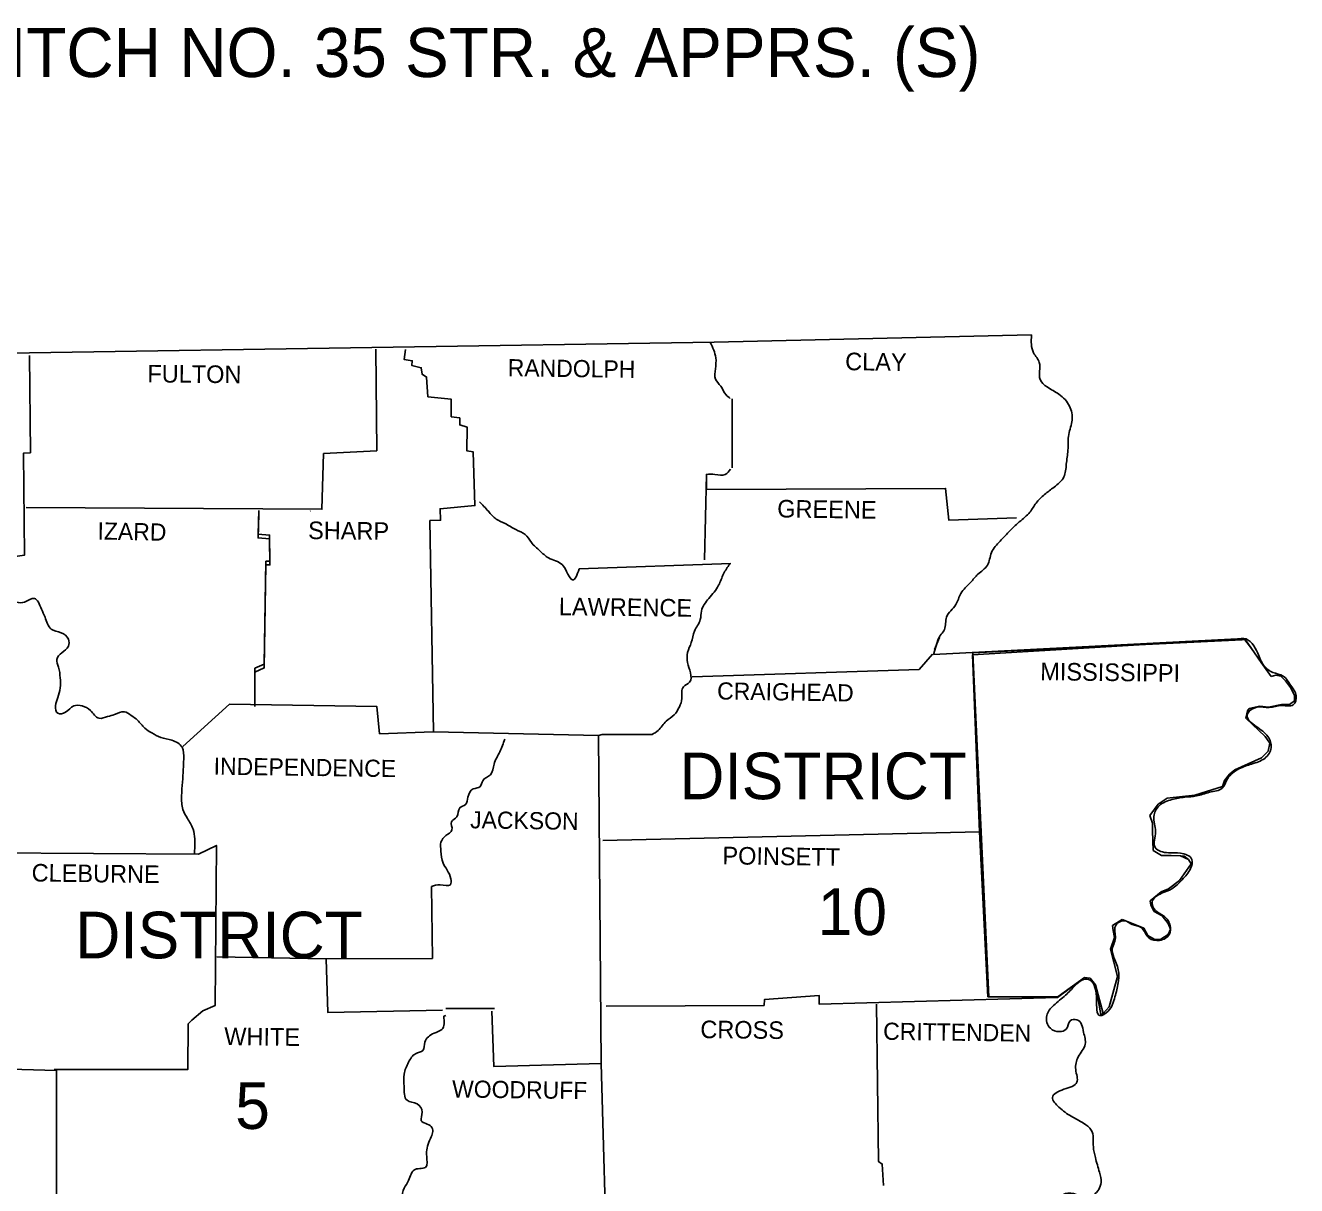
# Model space of a CAD drawing. Extents: x 166 to 3426, y 71 to 2074.
# Drawn here: x 2999.8 to 3303.9, y 1757.5 to 2035 of the extents above; entities that cross this region are included whole.
import ezdxf

# ---------------------------------------------------------------- set-up
doc = ezdxf.new("R2010")
doc.units = 0
for name, color, linetype in [('1', 7, 'Continuous'), ('2', 7, 'Continuous'), ('3', 7, 'Continuous'), ('R_Border', 7, 'Continuous'), ('S_MISC_BOUNDARY', 7, 'Continuous')]:
    doc.layers.add(name, color=color, linetype=linetype)

msp = doc.modelspace()

# ---------------------------------------------------------------- linework, layer by layer
at = {"layer": '1'}
for p, q in [((3217.27, 1885.68), (3218.45, 1888.52)), ((3216.98, 1884.51), (3218.15, 1888.13)), ((3100.35, 1799.78), (3112, 1799.78))]:
    msp.add_line(p, q, dxfattribs=at)
for points in [[(2703.71, 1956.42), (2861.92, 1956.32), (3000.75, 1956.61), (3164.54, 1959.16), (3240.46, 1960.92)], [(3000.75, 1956.03), (3000.95, 1932.74), (2999.28, 1932.64), (2999.58, 1908.28), (2992.73, 1907.3), (2993.32, 1900.75), (2995.66, 1897.71), (2995.47, 1889.98), (2982.16, 1889.5), (2981.67, 1877.56), (2969.54, 1877.17), (2968.95, 1862.69), (2969.64, 1861.51), (2969.93, 1838.42), (2990.87, 1837.05), (2990.58, 1785.49), (3007.21, 1785), (3007.21, 1732.56), (2994.1, 1731.58), (2993.12, 1720.04), (2971.11, 1719.94)], [(3083.62, 1957.49), (3083.82, 1933.23), (3071.1, 1932.55), (3070.71, 1919.24), (2999.97, 1919.63)], [(3090.67, 1957.4), (3090.37, 1955.05), (3092.33, 1954.76), (3092.23, 1953.58), (3094.48, 1953.09), (3094.68, 1951.53), (3095.75, 1950.84), (3096.05, 1946.15), (3101.63, 1945.56), (3101.63, 1941.35), (3103.68, 1941.06), (3103.68, 1939.39), (3105.44, 1938.9), (3105.34, 1933.23), (3106.91, 1932.94), (3107.3, 1920.12), (3098.98, 1919.34), (3099.08, 1916.6), (3096.54, 1916.5), (3097.42, 1866.01), (3136.85, 1865.13), (3137.53, 1786.66), (3111.8, 1785.98), (3111.31, 1799.19)], [(3168.84, 1945.66), (3168.84, 1929.12)], [(3162.19, 1907.11), (3162.68, 1927.56), (3162.68, 1923.94), (3219.91, 1924.23), (3220.7, 1916.6), (3236.84, 1917.18)], [(3055.64, 1918.95), (3055.44, 1913.27), (3058.18, 1913.07), (3058.28, 1906.81), (3057.3, 1906.81), (3056.91, 1882.16), (3054.66, 1881.18), (3054.66, 1872.96)], [(3067.87, 1918.75), (3067.97, 1918.85)], [(3055.64, 1918.06), (3055.44, 1912.39), (3058.18, 1912.19), (3058.28, 1905.93), (3057.3, 1905.93), (3056.91, 1881.28), (3054.66, 1880.3), (3054.66, 1872.08)], [(3132.25, 1904.95), (3168.55, 1906.23)], [(3216.98, 1884.51), (3291.24, 1888.32)], [(3159.25, 1879.12), (3213.55, 1880.89), (3216.78, 1884.6)], [(3226.37, 1884.41), (3228.04, 1842.04), (3229.99, 1802.61)], [(3037.44, 1862.49), (3048.6, 1872.57), (3083.82, 1872.08), (3084.5, 1865.52), (3097.32, 1866.01)], [(3149.67, 1865.33), (3137.73, 1865.33), (3136.85, 1865.13)], [(3228.04, 1842.04), (3137.92, 1839.99)], [(2990.87, 1837.05), (3041.16, 1836.76), (3045.46, 1838.81), (3045.17, 1800.56), (3042.24, 1799.29), (3039.59, 1797.04), (3038.71, 1796.16), (3038.62, 1785.2), (3006.62, 1785.2)], [(3096.93, 1829.03), (3097.12, 1811.81), (3071.69, 1811.71), (3045.56, 1812.2)], [(3071.69, 1811.71), (3072.08, 1798.89), (3099.57, 1799.38)], [(3138.71, 1800.36), (3176.47, 1800.56), (3176.57, 1801.93), (3189.68, 1802.91), (3189.68, 1800.85), (3246.63, 1802.42)], [(3203.38, 1800.85), (3203.87, 1763.18), (3204.75, 1762.6), (3205.04, 1757.51)], [(3100.35, 1798.11), (3099.86, 1798.01)], [(3137.53, 1786.66), (3139, 1733.05), (3115.71, 1732.95), (3115.62, 1730.8), (3108.87, 1730.41), (3108.28, 1719.25), (3100.06, 1719.25)]]:
    msp.add_lwpolyline(points, dxfattribs=at)
for points in [[(3163.59, 1959.15), (3164.93, 1955.44), (3164.83, 1952.8), (3164.83, 1950.35), (3166.1, 1948.69), (3167.37, 1946.63), (3168.35, 1945.75)], [(3240.46, 1960.92), (3240.95, 1956.61), (3242.32, 1954.36), (3242.52, 1950.25), (3244.18, 1948.49), (3247.02, 1946.73), (3249.56, 1943.89), (3250.15, 1940.57), (3249.36, 1937.14), (3249.17, 1933.33), (3248.78, 1930), (3248.19, 1926.97), (3245.84, 1924.52), (3243.59, 1922.76), (3241.54, 1920.71), (3240.07, 1918.55), (3237.53, 1916.21), (3234.98, 1913.76), (3232.93, 1911.61), (3230.87, 1908.87), (3229.89, 1905.83), (3227.64, 1903.68), (3225.88, 1901.73), (3223.53, 1899.08), (3222.36, 1896.44), (3220.11, 1893.41), (3219.62, 1890.47), (3218.15, 1888.13), (3218.06, 1887.73)], [(3168.45, 1928.83), (3167.18, 1927.56), (3164.73, 1927.56), (3162.68, 1927.56)], [(3108.38, 1921), (3110.53, 1918.75), (3112.39, 1916.89), (3114.54, 1915.81), (3117.08, 1914.35), (3119.33, 1913.17), (3120.8, 1911.31), (3122.86, 1909.26), (3124.91, 1907.6), (3128.14, 1906.03), (3129.22, 1904.37), (3130.68, 1902.31), (3132.25, 1904.95)], [(3168.25, 1906.13), (3166.79, 1903.78), (3165.61, 1901.04), (3163.26, 1897.91), (3161.5, 1894.88), (3161.21, 1892.82), (3159.84, 1890.08), (3159.06, 1887.34), (3158.18, 1884.99), (3158.18, 1882.55), (3158.86, 1880.1), (3158.67, 1877.85), (3157.2, 1876.78), (3156.81, 1873.94), (3156.22, 1871.98), (3154.95, 1870.03), (3153.09, 1868.56), (3151.13, 1866.31), (3149.67, 1865.33)], [(2995.66, 1897.71), (2999.58, 1897.03), (3001.93, 1897.91), (3003.59, 1895.37), (3004.47, 1893.41), (3005.94, 1890.57), (3008.29, 1889.69), (3010.05, 1888.13), (3010.05, 1886.46), (3008.48, 1884.9), (3007.31, 1883.33), (3007.7, 1881.47), (3008.09, 1878.93), (3008.09, 1876.48), (3007.5, 1874.23), (3007.01, 1872.18), (3007.5, 1870.42), (3009.36, 1870.71), (3011.32, 1872.18), (3013.37, 1872.18), (3015.33, 1871.1), (3017.38, 1869.24), (3019.44, 1869.63), (3021.1, 1870.12), (3023.45, 1870.81), (3025.11, 1869.93), (3026.58, 1868.75), (3028.34, 1866.89), (3030.01, 1865.72), (3032.16, 1864.64), (3034.8, 1863.96), (3037.25, 1862.3), (3037.64, 1859.46), (3037.54, 1857.01), (3037.34, 1853.98), (3037.15, 1850.65), (3037.44, 1847.42), (3038.52, 1845.27), (3039.89, 1842.73), (3040.28, 1840.38), (3040.18, 1836.66)], [(3290.16, 1888.22), (3291.24, 1888.32), (3294.57, 1884.8), (3296.03, 1881.86), (3298.19, 1880.2), (3300.63, 1879.32), (3302.49, 1877.07), (3303.76, 1874.62), (3303.08, 1872.47), (3300.34, 1872.28), (3297.31, 1871.79), (3294.37, 1871.88), (3292.02, 1869.93), (3294.18, 1867.29), (3297.01, 1864.84), (3297.8, 1862.2), (3296.23, 1859.65), (3293.1, 1858.28), (3290.07, 1857.11), (3287.33, 1854.76), (3286.05, 1852.51), (3283.02, 1851.53), (3279.89, 1850.65), (3277.15, 1850.36), (3274.02, 1849.77), (3270.99, 1848.3), (3269.72, 1845.76), (3270.11, 1842.14), (3270.01, 1838.32), (3273.24, 1837.05), (3276.08, 1836.95), (3278.81, 1835.49), (3278.52, 1833.33), (3276.47, 1830.6), (3274.02, 1828.44), (3271.57, 1827.37), (3269.32, 1825.31), (3270.11, 1823.26), (3272.16, 1821.89), (3273.63, 1819.64), (3273.43, 1817.58), (3271.09, 1816.11), (3268.54, 1816.7), (3266.68, 1819.15), (3264.53, 1819.93), (3262.67, 1820.81), (3260.52, 1819.54), (3260.52, 1816.7), (3259.74, 1813.67), (3260.42, 1811.42), (3261.3, 1808.29), (3261.2, 1805.94), (3260.42, 1802.61), (3258.76, 1799.19), (3256.8, 1798.11), (3256.02, 1801.83), (3255.63, 1804.86), (3254.45, 1806.62), (3252.89, 1806.72), (3250.83, 1805.25), (3248.58, 1803), (3245.74, 1800.56), (3244.08, 1798.11), (3244.96, 1795.08), (3247.11, 1794.3), (3248.78, 1794.88), (3249.66, 1796.84), (3251.32, 1797.13), (3252.89, 1794.1)], [(3114.44, 1864.25), (3113.27, 1861.22), (3111.9, 1858.28), (3111.02, 1855.74), (3109.16, 1854.27), (3108.57, 1852.9), (3106.91, 1852.32), (3105.64, 1850.36), (3105.05, 1848.6), (3103.68, 1847.82), (3103, 1845.66), (3101.72, 1844.49), (3101.82, 1842.53), (3100.35, 1841.16), (3099.18, 1839.6), (3099.18, 1837.44), (3099.67, 1834.61), (3100.65, 1832.94), (3101.53, 1830.79), (3101.43, 1829.42), (3098.98, 1829.42), (3096.93, 1829.03)], [(3099.86, 1798.01), (3099.37, 1794.79), (3097.52, 1793.91), (3095.36, 1791.75), (3094.87, 1789.8), (3093.11, 1789.01), (3091.45, 1786.96), (3090.37, 1784.12), (3090.37, 1781.19), (3091.06, 1777.86), (3093.5, 1776.98), (3094.68, 1775.02), (3094.48, 1772.97), (3096.83, 1771.6), (3097.22, 1770.42), (3096.83, 1769.15), (3095.75, 1765.53), (3095.85, 1763.09), (3095.66, 1762.01), (3093.02, 1761.32), (3091.45, 1758.68), (3090.37, 1756.82), (3089.98, 1754.38), (3090.28, 1752.62), (3089.49, 1751.25), (3089.2, 1749.19), (3088.22, 1747.43), (3087.34, 1745.77), (3088.32, 1743.81), (3088.03, 1742.44), (3087.44, 1740.29), (3087.93, 1739.6)], [(3252.89, 1794.1), (3253.28, 1791.26), (3251.62, 1788.23), (3251.03, 1785.2), (3251.32, 1782.16), (3248.19, 1780.5), (3245.45, 1778.54), (3247.02, 1776.2), (3249.95, 1774.04), (3252.89, 1772.38), (3254.75, 1770.72), (3255.24, 1766.71), (3255.72, 1764.16), (3256.7, 1760.64), (3257.09, 1758.19), (3255.33, 1755.26), (3253.28, 1754.67), (3251.13, 1755.36), (3248.58, 1755.55), (3246.53, 1753.59), (3245.06, 1750.86), (3243.59, 1748.12), (3242.52, 1745.77), (3241.44, 1743.22), (3239.29, 1740.29), (3236.65, 1739.8), (3233.51, 1739.02), (3231.66, 1736.86), (3231.95, 1733.24), (3233.71, 1730.8), (3235.08, 1727.76), (3236.06, 1725.12), (3235.57, 1721.8), (3234.2, 1719.35), (3232.44, 1717.88), (3231.66, 1714.75), (3230.38, 1712.4), (3229.21, 1711.62), (3226.86, 1711.82), (3224.32, 1712.31), (3222.16, 1712.11), (3220.11, 1711.03), (3218.06, 1711.72), (3215.9, 1714.07), (3214.14, 1715.83), (3212.19, 1716.51), (3210.13, 1715.44), (3209.74, 1712.21), (3210.72, 1708.88), (3211.6, 1704.38), (3210.72, 1701.64), (3210.42, 1697.14)]]:
    msp.add_spline(points, degree=3, dxfattribs=at)
at = {"layer": 'S_MISC_BOUNDARY'}
for p, q in [((3290.16, 1888.22), (3226.37, 1884.41)), ((3226.44, 1884.86), (3290.81, 1888.03)), ((3290.31, 1888.24), (3290.16, 1888.22)), ((3291.24, 1888.32), (3290.31, 1888.24)), ((3290.81, 1888.03), (3291.37, 1888.06)), ((3293.06, 1885.95), (3291.24, 1888.32)), ((3291.37, 1888.06), (3291.82, 1887.74)), ((3291.82, 1887.74), (3293.06, 1885.95)), ((3293.06, 1885.95), (3295.41, 1882.57)), ((3295.41, 1882.57), (3293.06, 1885.95)), ((3230.26, 1802.6), (3226.44, 1884.86)), ((3295.41, 1882.57), (3297.76, 1879.19)), ((3297.76, 1879.19), (3295.41, 1882.57)), ((3297.76, 1879.19), (3298.93, 1879.51)), ((3298.93, 1879.51), (3297.76, 1879.19)), ((3298.93, 1879.51), (3300.13, 1879.31)), ((3300.13, 1879.31), (3298.93, 1879.51)), ((3300.13, 1879.31), (3301.22, 1878.2)), ((3301.22, 1878.2), (3300.13, 1879.31)), ((3301.22, 1878.2), (3302.44, 1876.57)), ((3302.44, 1876.57), (3301.22, 1878.2)), ((3302.44, 1876.57), (3303.37, 1874.77)), ((3303.37, 1874.77), (3302.44, 1876.57)), ((3303.38, 1873.39), (3302.17, 1872.53)), ((3302.17, 1872.53), (3303.38, 1873.39)), ((3303.37, 1874.77), (3303.38, 1873.39)), ((3303.38, 1873.39), (3303.37, 1874.77)), ((3292.13, 1871.02), (3291.68, 1869.22)), ((3291.68, 1869.22), (3292.03, 1870.18)), ((3292.03, 1870.18), (3292.09, 1870.35)), ((3292.09, 1870.35), (3292.54, 1871.57)), ((3292.54, 1871.57), (3292.13, 1871.02)), ((3295.05, 1872.12), (3292.54, 1871.57)), ((3292.54, 1871.57), (3295.05, 1872.12)), ((3297.13, 1871.88), (3295.05, 1872.12)), ((3295.05, 1872.12), (3297.13, 1871.88)), ((3300.28, 1872.51), (3297.13, 1871.88)), ((3297.13, 1871.88), (3300.28, 1872.51)), ((3302.17, 1872.53), (3300.28, 1872.51)), ((3300.28, 1872.51), (3302.17, 1872.53)), ((3291.68, 1869.22), (3296.38, 1864.85)), ((3296.38, 1864.85), (3291.68, 1869.22)), ((3296.38, 1864.85), (3297.46, 1863.25)), ((3297.46, 1863.25), (3296.38, 1864.85)), ((3297.04, 1861.36), (3295.44, 1859.75)), ((3295.44, 1859.75), (3297.04, 1861.36)), ((3297.46, 1863.25), (3297.04, 1861.36)), ((3297.04, 1861.36), (3297.46, 1863.25)), ((3295.44, 1859.75), (3289.06, 1856.92)), ((3289.06, 1856.92), (3295.44, 1859.75)), ((3287.8, 1855.85), (3286.65, 1854.36)), ((3286.65, 1854.36), (3287.8, 1855.85)), ((3289.06, 1856.92), (3287.8, 1855.85)), ((3287.8, 1855.85), (3289.06, 1856.92)), ((3286.16, 1852.93), (3279.52, 1850.83)), ((3286.65, 1854.36), (3286.16, 1852.93)), ((3286.16, 1852.93), (3286.65, 1854.36)), ((3272.94, 1850.13), (3270.72, 1848.72)), ((3270.72, 1848.72), (3272.94, 1850.13)), ((3279.52, 1850.83), (3272.94, 1850.13)), ((3272.94, 1850.13), (3279.52, 1850.83)), ((3270.72, 1848.72), (3268.77, 1845.96)), ((3268.77, 1845.96), (3270.72, 1848.72)), ((3268.77, 1845.96), (3269.38, 1844.17)), ((3269.38, 1844.17), (3268.77, 1845.96)), ((3269.38, 1844.17), (3269.38, 1842.29)), ((3269.38, 1842.29), (3269.38, 1844.17)), ((3269.38, 1842.29), (3269.56, 1837.62)), ((3269.56, 1837.62), (3269.38, 1842.29)), ((3269.56, 1837.62), (3271.52, 1836.44)), ((3271.52, 1836.44), (3269.56, 1837.62)), ((3271.52, 1836.44), (3273.82, 1836.37)), ((3273.82, 1836.37), (3271.52, 1836.44)), ((3273.82, 1836.37), (3276.11, 1836.3)), ((3276.11, 1836.3), (3273.82, 1836.37)), ((3278.67, 1834.41), (3275.86, 1830.41)), ((3275.86, 1830.41), (3278.67, 1834.41)), ((3276.11, 1836.3), (3276.94, 1836.27)), ((3278.02, 1835.47), (3276.11, 1836.3)), ((3276.94, 1836.27), (3278.02, 1835.47)), ((3278.02, 1835.47), (3278.67, 1834.41)), ((3278.67, 1834.41), (3278.02, 1835.47)), ((3271.5, 1827.68), (3268.87, 1825.55)), ((3268.87, 1825.55), (3271.5, 1827.68)), ((3273.22, 1828.41), (3271.5, 1827.68)), ((3271.5, 1827.68), (3273.22, 1828.41)), ((3275.86, 1830.41), (3273.22, 1828.41)), ((3273.22, 1828.41), (3275.86, 1830.41)), ((3268.87, 1825.55), (3268.96, 1824.55)), ((3268.96, 1824.55), (3268.87, 1825.55)), ((3268.96, 1824.55), (3269.77, 1823.02)), ((3269.77, 1823.02), (3268.96, 1824.55)), ((3269.77, 1823.02), (3271.69, 1821.96)), ((3271.69, 1821.96), (3269.77, 1823.02)), ((3271.69, 1821.96), (3273.18, 1820.16)), ((3273.18, 1820.16), (3271.69, 1821.96)), ((3262.17, 1821.14), (3259.84, 1819.64)), ((3259.84, 1819.64), (3262.17, 1821.14)), ((3259.84, 1819.64), (3259.96, 1818.51)), ((3259.96, 1818.51), (3259.84, 1819.64)), ((3259.96, 1818.51), (3260.3, 1816.83)), ((3260.3, 1816.83), (3259.96, 1818.51)), ((3264.4, 1820.23), (3262.17, 1821.14)), ((3262.17, 1821.14), (3264.4, 1820.23)), ((3267.29, 1819.04), (3264.4, 1820.23)), ((3264.4, 1820.23), (3267.29, 1819.04)), ((3268.24, 1817.29), (3267.29, 1819.04)), ((3267.29, 1819.04), (3268.24, 1817.29)), ((3273.69, 1818.75), (3273.11, 1817.5)), ((3273.11, 1817.5), (3273.69, 1818.75)), ((3273.18, 1820.16), (3273.69, 1818.75)), ((3273.69, 1818.75), (3273.18, 1820.16)), ((3260.3, 1816.83), (3259.31, 1814)), ((3259.31, 1814), (3260.3, 1816.83)), ((3269.98, 1816.31), (3268.24, 1817.29)), ((3268.24, 1817.29), (3269.98, 1816.31)), ((3271.38, 1816.37), (3269.98, 1816.31)), ((3269.98, 1816.31), (3271.38, 1816.37)), ((3273.11, 1817.5), (3271.38, 1816.37)), ((3271.38, 1816.37), (3273.11, 1817.5)), ((3259.31, 1814), (3261.05, 1807.5)), ((3261.05, 1807.5), (3259.31, 1814)), ((3246.63, 1802.42), (3253.09, 1807.19)), ((3253.09, 1807.19), (3246.81, 1802.72)), ((3254.51, 1807.09), (3253.09, 1807.19)), ((3253.09, 1807.19), (3254.51, 1807.09)), ((3255.79, 1805.51), (3254.51, 1807.09)), ((3254.51, 1807.09), (3255.79, 1805.51)), ((3261.05, 1807.5), (3258.99, 1800.18)), ((3258.99, 1800.18), (3261.05, 1807.5)), ((3257.01, 1798.41), (3255.79, 1805.51)), ((3255.79, 1805.51), (3257.56, 1798.6)), ((3229.99, 1802.61), (3246.63, 1802.42)), ((3246.81, 1802.72), (3230.26, 1802.6)), ((3258.99, 1800.18), (3257.56, 1798.6)), ((3257.56, 1798.6), (3258.99, 1800.18)), ((3257.56, 1798.6), (3257.01, 1798.41))]:
    msp.add_line(p, q, dxfattribs=at)
for points in [[(3226.37, 1884.41), (3228.25, 1842.05), (3229.99, 1802.61)], [(3279.52, 1850.83), (3281.02, 1851.31), (3286.16, 1852.93)]]:
    msp.add_lwpolyline(points, dxfattribs=at)

# ---------------------------------------------------------------- texts
at = {"layer": '2'}
for s, height, rotation, p in [('CLAY', 4.206, 359.2258, (3195.85, 1952.5)), ('FULTON', 4.206, 359.4996, (3028.93, 1949.57)), ('RANDOLPH', 4.109, 359.2583, (3115.13, 1951.04)), ('GREENE', 4.207, 359.2361, (3179.6, 1917.28)), ('IZARD', 4.108, 358.9258, (3016.99, 1912)), ('SHARP', 4.206, 359.3905, (3067.38, 1912.1)), ('LAWRENCE', 4.207, 359.2678, (3127.36, 1893.9)), ('MISSISSIPPI', 4.2062, 359.3097, (3242.52, 1878.34)), ('CRAIGHEAD', 4.109, 359.1159, (3165.22, 1873.74)), ('INDEPENDENCE', 4.1081, 359.2187, (3044.78, 1855.74)), ('JACKSON', 4.108, 359.1352, (3106.13, 1842.92)), ('POINSETT', 4.206, 359.1987, (3166.49, 1834.31)), ('CLEBURNE', 4.206, 359.2535, (3001.24, 1830.2)), ('WHITE', 4.207, 359.3139, (3047.32, 1791.07)), ('CROSS', 4.206, 359.3839, (3161.21, 1792.73)), ('CRITTENDEN', 4.109, 359.213, (3204.94, 1792.34)), ('WOODRUFF', 4.108, 359.2748, (3101.82, 1778.54))]:
    msp.add_text(s, height=height, rotation=rotation, dxfattribs=at).set_placement(p)
at = {"layer": '3'}
for s, height, p in [('DISTRICT', 11.154, (3156.22, 1849.87)), ('10', 11.154, (3189.29, 1817.39)), ('DISTRICT', 11.154, (3011.71, 1811.81)), ('5', 11.15, (3049.97, 1771.01))]:
    msp.add_text(s, height=height, dxfattribs=at).set_placement(p)
at = {"layer": 'R_Border'}
msp.add_text('DITCH NO. 35 STR. & APPRS. (S)', height=11.724, dxfattribs=at).set_placement((2984.31, 2022.61))

doc.saveas('drawing.dxf')
